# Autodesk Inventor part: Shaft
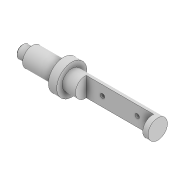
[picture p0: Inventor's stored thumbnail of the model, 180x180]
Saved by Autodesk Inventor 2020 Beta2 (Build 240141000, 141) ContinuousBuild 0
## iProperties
Created: 2019-03
Part Number: Shaft
Material: Generic
Document SubType Name: Modeling
Designer: LENOVO-CADCIM
Density: 1 g/cm^3
Appearance: Default
Author: LENOVO-CADCIM
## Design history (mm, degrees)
sketch "Sketch1"
  geometry: L1 (284.311, 0)-(1023.188, 0); L2 (391.676, 0)-(391.676, -18); L3 (391.676, -18)-(420.576, -18); L4 (420.576, -18)-(420.576, -28); L5 (420.576, -28)-(510.376, -28); L6 (510.376, -28)-(510.376, -43.6); L7 (510.376, -43.6)-(534.376, -43.6); L8 (534.376, -43.6)-(534.376, -28); L9 (534.376, -28)-(781.476, -28); L10 (781.476, -28)-(781.476, 0); L11 (391.676, 0)-(781.476, 0); 1 further point
  constraints: 22 end point, 8 perpendicular, 5 point on line, 1 collinear, 1 horizontal
  dimensions: "d0" = 28.9 distance of L2.end L3.end; "d1" = 89.8 distance of L4.end L5.end; "d2" = 24 distance of L6.end L7.end; "d3" = 247.1 distance of L8.end L9.end; "d4" = 56 diameter of L9 L1; "d5" = 87.2 diameter of L7 L1; "d6" = 36 diameter of L3 L1
revolve "Revolution1" sketch "Sketch1" stored, may be unused: angle "d7" = 90 deg
sketch "Sketch4"
  geometry: L1 (-781.476, 28)-(-534.376, 28) reference; L2 (-572.576, 28)-(-766.376, 28); L3 (-766.376, 28)-(-766.376, -3.1); L4 (-766.376, -3.1)-(-572.576, -3.1); L5 (-572.576, -3.1)-(-572.576, 28); L6 (-781.476, -28)-(-534.376, -28) reference; 2 further points
  constraints: 8 end point, 2 parallel, 1 horizontal, 1 perpendicular, 1 point on line
  dimensions: "d16" = 24.9 distance between parallel lines of L6 L4; "d17" = 15.1 distance from line of L1.start L3; "d40" = 193.8 distance of L3.end L4.end
extrude "Extrusion3" cut sketch "Sketch4" stored distance "d18" = 257; taper "d19" = 0 deg
sketch "Sketch6"
  geometry: L1 (-180.9, 45.828)-(-180.9, 9.828) reference; L2 (-180.9, 27.828)-(320.546, 27.828); L3 (0, 55.828)-(0, -0.172) reference; 5 further points
  constraints: 2 end point, 2 point on line, 1 horizontal, 1 midpoint
  dimensions: "d24" = 100 distance of point (46.9, 27.828) point (146.9, 27.828); "d25" = 46.9 distance from line of L3 point (46.9, 27.828)
hole "Hole1" sketch "Sketch6" at (46.9, 27.828), (146.9, 27.828) diameter "d26" = 12.5; stored, may be unused: countersink angle "d30" = 90 deg, drill point angle "d32" = 118 deg; dims "d27" = 6, "d28" = 100, "d29" = 25, "d31" = 310
chamfer "Chamfer1" distance "d33" = 3; stored, may be unused: second distance "d34" = 2, angle "d35" = 45 deg
sketch "Sketch7"
  geometry: L1 (8, -22)-(-8, -22); L2 (-8, -22)-(-8, -26.833); L3 (8, -26.833)-(8, -22); L4 (0, 0)-(0, 64); C1 r 28 at (0, 0) reference; A1 r 28 centre (0, 0) between (-8, -26.833) and (8, -26.833); A2 r 28 centre (0, 0) between (8, -26.833) and (-8, -26.833) reference; 4 further points
  constraints: 8 end point, 3 point on circle, 1 centre point, 1 coincident, 1 concentric, 1 horizontal, 1 parallel, 1 perpendicular, 1 vertical, 1 other
  dimensions: "d36" = 16 distance between parallel lines of L3 L2; "d37" = 50 distance from line of point (0, 28) L1
extrude "Extrusion5" cut sketch "Sketch7" distance "d38" = 62.5; taper "d39" = 0 deg
body "Solid1"
